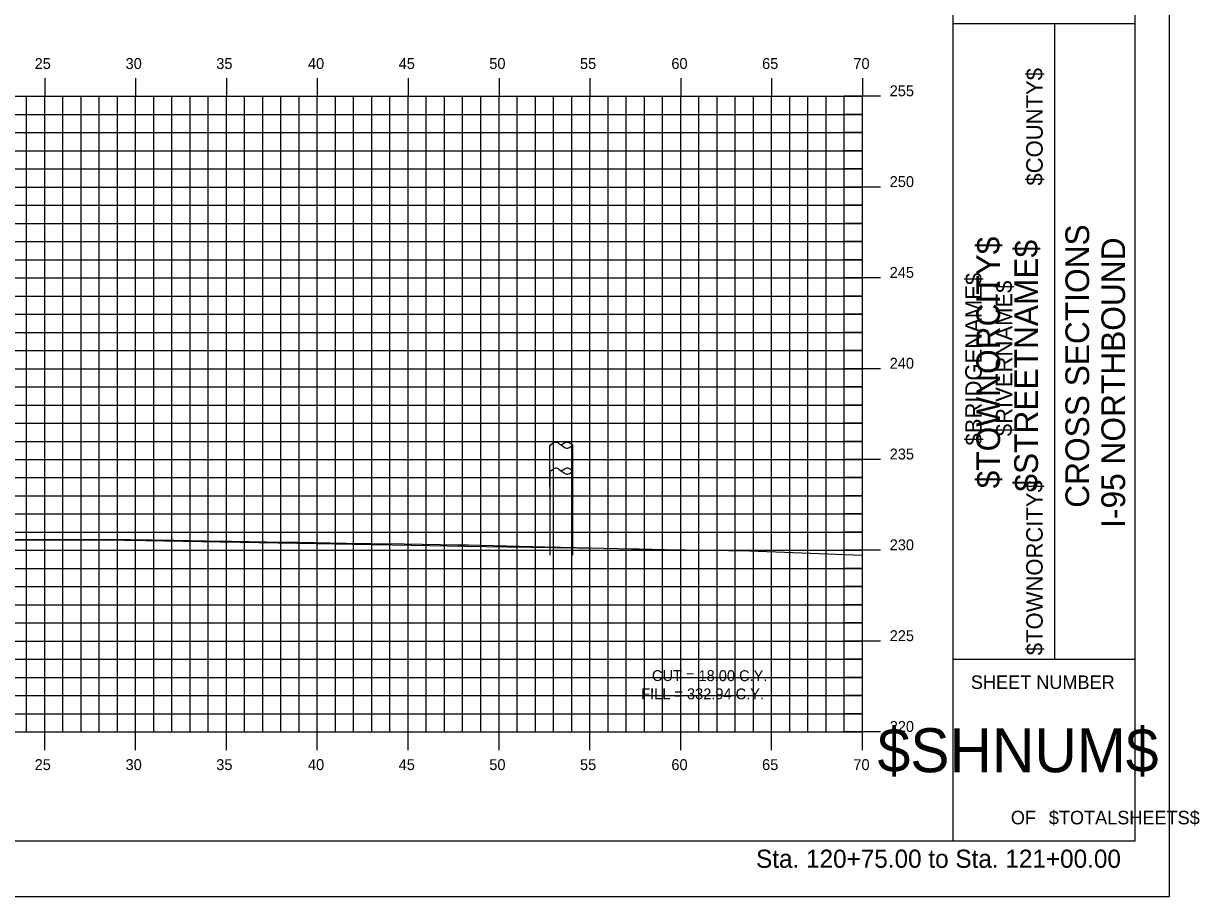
# Model space of a CAD drawing. Extents: x -22 to 1480, y -1511 to 8.
# Drawn here: x 877.3 to 942, y -1511.4 to -1463.3 of the extents above; entities that cross this region are included whole.
import ezdxf

# ---------------------------------------------------------------- set-up
doc = ezdxf.new("R2010")
doc.units = 0
for name, color, linetype in [('ANNOTATION', 7, 'Continuous'), ('BORDER', 7, 'Continuous'), ('BRIDGE_TITLE', 7, 'Continuous'), ('D_Roadway_Centerline', 7, 'Continuous'), ('H_V ANNOTATION', 7, 'Continuous'), ('HIGHWAY_TITLE', 7, 'Continuous'), ('MAJOR', 7, 'Continuous'), ('MINOR', 7, 'Continuous'), ('PLOT BOUNDARY', 7, 'Continuous'), ('S_Roadway_Centerline', 7, 'Continuous'), ('S_Utilities_Pole_Joint', 7, 'Continuous'), ('S_Utilities_Pole_Power', 7, 'Continuous')]:
    doc.layers.add(name, color=color, linetype=linetype)

msp = doc.modelspace()

# ---------------------------------------------------------------- linework, layer by layer
at = {"layer": 'BORDER'}
for p, q in [((928.426, -1508.328), (928.426, -1403.328)), ((938.426, -1508.328), (938.426, -1403.328)), ((928.426, -1463.328), (938.426, -1463.328)), ((934.017, -1498.328), (934.017, -1463.328)), ((928.426, -1498.328), (938.426, -1498.328)), ((778.426, -1508.331), (938.426, -1508.331))]:
    msp.add_line(p, q, dxfattribs=at)
at = {"layer": 'D_Roadway_Centerline'}
msp.add_lwpolyline([(876.73, -1491.746), (877.556, -1491.749), (881.861, -1491.745), (882.7, -1491.762), (882.824, -1491.764), (882.99, -1491.767), (888.092, -1491.859), (889.171, -1491.88), (893.36, -1491.953), (895.356, -1491.992), (898.629, -1492.046), (901.546, -1492.096), (903.897, -1492.133), (907.74, -1492.2), (909.165, -1492.221)], dxfattribs=at)
at = {"layer": 'MAJOR'}
for p, q in [((878.426, -1466.329), (878.426, -1467.331)), ((883.426, -1466.329), (883.426, -1467.331)), ((888.426, -1466.329), (888.426, -1467.331)), ((893.426, -1466.329), (893.426, -1467.331)), ((898.426, -1466.329), (898.426, -1467.331)), ((903.426, -1466.329), (903.426, -1467.331)), ((908.426, -1466.329), (908.426, -1467.331)), ((913.426, -1466.329), (913.426, -1467.331)), ((918.426, -1466.329), (918.426, -1467.331)), ((923.426, -1466.329), (923.426, -1467.331)), ((783.426, -1467.331), (923.426, -1467.331)), ((783.426, -1467.331), (923.426, -1467.331)), ((878.426, -1502.331), (878.426, -1467.331)), ((883.426, -1502.331), (883.426, -1467.331)), ((888.426, -1502.331), (888.426, -1467.331)), ((893.426, -1502.331), (893.426, -1467.331)), ((898.426, -1502.331), (898.426, -1467.331)), ((903.426, -1502.331), (903.426, -1467.331)), ((908.426, -1502.331), (908.426, -1467.331)), ((913.426, -1502.331), (913.426, -1467.331)), ((918.426, -1502.331), (918.426, -1467.331)), ((924.428, -1467.331), (922.424, -1467.331)), ((923.426, -1502.331), (923.426, -1467.331)), ((923.426, -1502.331), (923.426, -1467.331)), ((783.426, -1472.331), (923.426, -1472.331)), ((924.428, -1472.331), (922.424, -1472.331)), ((783.426, -1477.331), (923.426, -1477.331)), ((924.428, -1477.331), (922.424, -1477.331)), ((783.426, -1482.331), (923.426, -1482.331)), ((924.428, -1482.331), (922.424, -1482.331)), ((783.426, -1487.331), (923.426, -1487.331)), ((924.428, -1487.331), (922.424, -1487.331)), ((783.426, -1492.331), (923.426, -1492.331)), ((924.428, -1492.331), (922.424, -1492.331)), ((783.426, -1497.331), (923.426, -1497.331)), ((924.428, -1497.331), (922.424, -1497.331)), ((783.426, -1502.331), (923.426, -1502.331)), ((783.426, -1502.331), (923.426, -1502.331)), ((878.426, -1503.333), (878.426, -1502.331)), ((883.426, -1503.333), (883.426, -1502.331)), ((888.426, -1503.333), (888.426, -1502.331)), ((893.426, -1503.333), (893.426, -1502.331)), ((898.426, -1503.333), (898.426, -1502.331)), ((903.426, -1503.333), (903.426, -1502.331)), ((908.426, -1503.333), (908.426, -1502.331)), ((913.426, -1503.333), (913.426, -1502.331)), ((918.426, -1503.333), (918.426, -1502.331)), ((924.428, -1502.331), (922.424, -1502.331)), ((923.426, -1503.333), (923.426, -1502.331))]:
    msp.add_line(p, q, dxfattribs=at)
at = {"layer": 'MINOR'}
for p, q in [((877.426, -1502.331), (877.426, -1467.331)), ((879.426, -1502.331), (879.426, -1467.331)), ((880.426, -1502.331), (880.426, -1467.331)), ((881.426, -1502.331), (881.426, -1467.331)), ((882.426, -1502.331), (882.426, -1467.331)), ((884.426, -1502.331), (884.426, -1467.331)), ((885.426, -1502.331), (885.426, -1467.331)), ((886.426, -1502.331), (886.426, -1467.331)), ((887.426, -1502.331), (887.426, -1467.331)), ((889.426, -1502.331), (889.426, -1467.331)), ((890.426, -1502.331), (890.426, -1467.331)), ((891.426, -1502.331), (891.426, -1467.331)), ((892.426, -1502.331), (892.426, -1467.331)), ((894.426, -1502.331), (894.426, -1467.331)), ((895.426, -1502.331), (895.426, -1467.331)), ((896.426, -1502.331), (896.426, -1467.331)), ((897.426, -1502.331), (897.426, -1467.331)), ((899.426, -1502.331), (899.426, -1467.331)), ((900.426, -1502.331), (900.426, -1467.331)), ((901.426, -1502.331), (901.426, -1467.331)), ((902.426, -1502.331), (902.426, -1467.331)), ((904.426, -1502.331), (904.426, -1467.331)), ((905.426, -1502.331), (905.426, -1467.331)), ((906.426, -1502.331), (906.426, -1467.331)), ((907.426, -1502.331), (907.426, -1467.331)), ((909.426, -1502.331), (909.426, -1467.331)), ((910.426, -1502.331), (910.426, -1467.331)), ((911.426, -1502.331), (911.426, -1467.331)), ((912.426, -1502.331), (912.426, -1467.331)), ((914.426, -1502.331), (914.426, -1467.331)), ((915.426, -1502.331), (915.426, -1467.331)), ((916.426, -1502.331), (916.426, -1467.331)), ((917.426, -1502.331), (917.426, -1467.331)), ((919.426, -1502.331), (919.426, -1467.331)), ((920.426, -1502.331), (920.426, -1467.331)), ((921.426, -1502.331), (921.426, -1467.331)), ((922.426, -1502.331), (922.426, -1467.331)), ((783.426, -1468.331), (923.426, -1468.331)), ((923.426, -1468.331), (922.424, -1468.331)), ((783.426, -1469.331), (923.426, -1469.331)), ((923.426, -1469.331), (922.424, -1469.331)), ((783.426, -1470.331), (923.426, -1470.331)), ((923.426, -1470.331), (922.424, -1470.331)), ((783.426, -1471.331), (923.426, -1471.331)), ((923.426, -1471.331), (922.424, -1471.331)), ((783.426, -1473.331), (923.426, -1473.331)), ((923.426, -1473.331), (922.424, -1473.331)), ((783.426, -1474.331), (923.426, -1474.331)), ((923.426, -1474.331), (922.424, -1474.331)), ((783.426, -1475.331), (923.426, -1475.331)), ((923.426, -1475.331), (922.424, -1475.331)), ((783.426, -1476.331), (923.426, -1476.331)), ((923.426, -1476.331), (922.424, -1476.331)), ((783.426, -1478.331), (923.426, -1478.331)), ((923.426, -1478.331), (922.424, -1478.331)), ((783.426, -1479.331), (923.426, -1479.331)), ((923.426, -1479.331), (922.424, -1479.331)), ((783.426, -1480.331), (923.426, -1480.331)), ((923.426, -1480.331), (922.424, -1480.331)), ((783.426, -1481.331), (923.426, -1481.331)), ((923.426, -1481.331), (922.424, -1481.331)), ((783.426, -1483.331), (923.426, -1483.331)), ((923.426, -1483.331), (922.424, -1483.331)), ((783.426, -1484.331), (923.426, -1484.331)), ((923.426, -1484.331), (922.424, -1484.331)), ((783.426, -1485.331), (923.426, -1485.331)), ((923.426, -1485.331), (922.424, -1485.331)), ((783.426, -1486.331), (923.426, -1486.331)), ((923.426, -1486.331), (922.424, -1486.331)), ((783.426, -1488.331), (923.426, -1488.331)), ((923.426, -1488.331), (922.424, -1488.331)), ((783.426, -1489.331), (923.426, -1489.331)), ((923.426, -1489.331), (922.424, -1489.331)), ((783.426, -1490.331), (923.426, -1490.331)), ((923.426, -1490.331), (922.424, -1490.331)), ((783.426, -1491.331), (923.426, -1491.331)), ((923.426, -1491.331), (922.424, -1491.331)), ((783.426, -1493.331), (923.426, -1493.331)), ((923.426, -1493.331), (922.424, -1493.331)), ((783.426, -1494.331), (923.426, -1494.331)), ((923.426, -1494.331), (922.424, -1494.331)), ((783.426, -1495.331), (923.426, -1495.331)), ((923.426, -1495.331), (922.424, -1495.331)), ((783.426, -1496.331), (923.426, -1496.331)), ((923.426, -1496.331), (922.424, -1496.331)), ((783.426, -1498.331), (923.426, -1498.331)), ((923.426, -1498.331), (922.424, -1498.331)), ((783.426, -1499.331), (923.426, -1499.331)), ((923.426, -1499.331), (922.424, -1499.331)), ((783.426, -1500.331), (923.426, -1500.331)), ((923.426, -1500.331), (922.424, -1500.331)), ((783.426, -1501.331), (923.426, -1501.331)), ((923.426, -1501.331), (922.424, -1501.331))]:
    msp.add_line(p, q, dxfattribs=at)
at = {"layer": 'PLOT BOUNDARY'}
msp.add_lwpolyline([(770.333, -1511.39), (940.333, -1511.39), (940.333, -1401.39), (770.333, -1401.39)], close=True, dxfattribs=at)
at = {"layer": 'S_Roadway_Centerline'}
msp.add_lwpolyline([(876.177, -1491.736), (877.429, -1491.738), (877.868, -1491.738), (878.193, -1491.736), (879.976, -1491.728), (881.924, -1491.736), (882.373, -1491.738), (882.52, -1491.737), (882.956, -1491.735), (882.99, -1491.735), (883.17, -1491.735), (885.539, -1491.777), (887.305, -1491.808), (888.704, -1491.833), (891.61, -1491.876), (891.869, -1491.88), (892.351, -1491.888), (895.035, -1491.931), (896.399, -1491.952), (898.2, -1491.979), (901.173, -1492.025), (901.366, -1492.028), (901.745, -1492.034), (904.532, -1492.103), (905.948, -1492.134), (907.697, -1492.173), (910.722, -1492.247), (910.862, -1492.25), (911.139, -1492.258), (912.527, -1492.286), (917.221, -1492.366), (917.688, -1492.386), (919.146, -1492.438), (923.426, -1492.601)], dxfattribs=at)
msp.add_lwpolyline([(876.177, -1491.736), (877.429, -1491.738), (877.868, -1491.738), (878.193, -1491.736), (879.976, -1491.728), (881.924, -1491.736), (882.373, -1491.738), (882.52, -1491.737), (882.956, -1491.735), (882.99, -1491.735), (883.17, -1491.735), (885.539, -1491.777), (887.305, -1491.808), (888.704, -1491.833), (891.61, -1491.876), (891.869, -1491.88), (892.351, -1491.888), (895.035, -1491.931), (896.399, -1491.952), (898.2, -1491.979), (901.173, -1492.025), (901.366, -1492.028), (901.745, -1492.034), (904.532, -1492.103), (905.948, -1492.134), (907.697, -1492.173), (910.722, -1492.247), (910.862, -1492.25), (911.139, -1492.258), (912.527, -1492.286), (917.221, -1492.366), (917.688, -1492.386), (919.146, -1492.438), (923.426, -1492.601)], dxfattribs=at)
at = {"layer": 'S_Utilities_Pole_Joint'}
for p, q in [((906.235, -1486.548), (906.392, -1486.438)), ((906.704, -1486.438), (906.86, -1486.548)), ((907.017, -1486.438), (906.86, -1486.548)), ((907.485, -1486.548), (907.329, -1486.438)), ((906.86, -1486.548), (907.017, -1486.659)), ((907.329, -1486.659), (907.485, -1486.548)), ((906.243, -1487.974), (906.399, -1487.864)), ((906.711, -1487.864), (906.867, -1487.974)), ((907.024, -1487.864), (906.867, -1487.974)), ((906.867, -1487.974), (907.024, -1488.085)), ((907.493, -1487.974), (907.337, -1487.864)), ((907.337, -1488.085), (907.493, -1487.974))]:
    msp.add_line(p, q, dxfattribs=at)
for centre, start, end in [((906.548, -1486.659), 90, 125.26439), ((906.548, -1486.659), 54.73561, 90), ((907.173, -1486.659), 90, 125.26439), ((907.173, -1486.659), 54.73561, 90), ((907.173, -1486.438), 234.73561, 270), ((907.173, -1486.438), 270, 305.26439), ((906.555, -1488.085), 90, 125.26439), ((906.555, -1488.085), 54.73561, 90), ((907.18, -1488.085), 90, 125.26439), ((907.18, -1487.864), 234.73561, 270), ((907.18, -1488.085), 54.73561, 90), ((907.18, -1487.864), 270, 305.26439)]:
    msp.add_arc(centre, 0.271, start, end, dxfattribs=at)
at = {"layer": 'S_Utilities_Pole_Power'}
for p, q in [((906.235, -1491.167), (906.232, -1486.548)), ((907.485, -1491.167), (907.482, -1486.548)), ((906.243, -1492.593), (906.24, -1487.974)), ((907.493, -1492.593), (907.49, -1487.974))]:
    msp.add_line(p, q, dxfattribs=at)

# ---------------------------------------------------------------- texts
at = {"layer": 'ANNOTATION'}
for s, p in [('CUT = 18.00 C.Y.', (911.842, -1499.527)), ('FILL = 332.94 C.Y.', (911.252, -1500.528))]:
    msp.add_text(s, height=0.6, rotation=359.92408, dxfattribs=at).set_placement(p)
at = {"layer": 'BORDER'}
for s, height, rotation, p in [('CROSS SECTIONS', 1.30428, 90, (935.902, -1489.989)), ('I-95 NORTHBOUND', 1.30428, 90, (937.88, -1491.095)), ('SHEET NUMBER', 0.74527, 360, (929.392, -1499.965)), ('$SHNUM$', 2.4194, 360, (924.259, -1504.549)), ('OF', 0.7453, 360, (931.593, -1507.418)), ('$TOTALSHEETS$', 0.74527, 360, (933.683, -1507.418))]:
    msp.add_text(s, height=height, rotation=rotation, dxfattribs=at).set_placement(p)
at = {"layer": 'BRIDGE_TITLE'}
for s, height, p in [('$COUNTY$', 0.9072, (933.346, -1472.249)), ('$BRIDGENAME$', 0.90716, (929.992, -1486.56)), ('$RIVERNAME$', 0.90716, (931.669, -1486.045)), ('$TOWNORCITY$', 0.90716, (933.346, -1498.107))]:
    msp.add_text(s, height=height, rotation=90, dxfattribs=at).set_placement(p)
at = {"layer": 'D_Roadway_Centerline'}
for s, p in [('C', (881.856, -1491.745)), ('L', (881.861, -1491.753))]:
    msp.add_text(s, height=0.0146, dxfattribs=at).set_placement(p)
at = {"layer": 'H_V ANNOTATION'}
for s, height, p in [('25', 0.6, (877.872, -1465.831)), ('30', 0.6, (882.875, -1465.831)), ('35', 0.6, (887.867, -1465.831)), ('40', 0.6, (892.912, -1465.831)), ('45', 0.6, (897.904, -1465.831)), ('50', 0.6, (902.891, -1465.831)), ('55', 0.6, (907.883, -1465.831)), ('60', 0.6, (912.912, -1465.831)), ('65', 0.6, (917.904, -1465.831)), ('70', 0.6, (922.928, -1465.831)), ('255', 0.6, (924.926, -1467.331)), ('250', 0.6, (924.926, -1472.331)), ('245', 0.6, (924.926, -1477.331)), ('240', 0.6, (924.926, -1482.331)), ('235', 0.6, (924.926, -1487.331)), ('230', 0.6, (924.926, -1492.331)), ('225', 0.6, (924.926, -1497.331)), ('220', 0.6, (924.926, -1502.331)), ('25', 0.6, (877.872, -1504.431)), ('30', 0.6, (882.875, -1504.431)), ('35', 0.6, (887.867, -1504.431)), ('40', 0.6, (892.912, -1504.431)), ('45', 0.6, (897.904, -1504.431)), ('50', 0.6, (902.891, -1504.431)), ('55', 0.6, (907.883, -1504.431)), ('60', 0.6, (912.912, -1504.431)), ('65', 0.6, (917.904, -1504.431)), ('70', 0.6, (922.928, -1504.431)), ('Sta. 120+75.00 to Sta. 121+00.00', 1.0002, (917.572, -1509.811))]:
    msp.add_text(s, height=height, dxfattribs=at).set_placement(p)
at = {"layer": 'HIGHWAY_TITLE'}
for s, p in [('$TOWNORCITY$', (930.999, -1488.92)), ('$STREETNAME$', (933.086, -1489.1))]:
    msp.add_text(s, height=1.30428, rotation=90, dxfattribs=at).set_placement(p)

doc.saveas('drawing.dxf')
